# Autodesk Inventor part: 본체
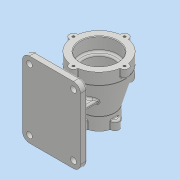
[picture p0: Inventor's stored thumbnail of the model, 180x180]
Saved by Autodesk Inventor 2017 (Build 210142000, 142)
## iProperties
Part Number: 본체
Material: 일반
Document SubType Name: Modeling
Designer: 222
Density: 1 g/cm^3
Appearance: 기본값
Mass: 385.863 g
Surface Area: 850.637 cm^2
Volume: 385.863 cm^3
Author: 222
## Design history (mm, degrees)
sketch "스케치2"
  geometry: L1 (0, 0)-(44, 0); L2 (44, 0)-(44, -20); L3 (44, -20)-(27.5, -78); L4 (27.5, -78)-(27.5, -100); L5 (27.5, -100)-(0, -100); L6 (0, -100)-(0, 0)
  constraints: 12 end point, 3 perpendicular, 1 horizontal, 1 parallel
  dimensions: "d0" = 88 diameter of L2 L6; "d1" = 55 diameter of L4 L6; "d2" = 100 distance of L5.end L1.start; "d4" = 20 distance of L1.end L2.end; "d5" = 22 distance of L3.end L4.end
revolve "회전1" sketch "스케치2" stored, may be unused: angle "d6" = 90 deg
node "작업 평면1"
sketch "스케치3"
  geometry: L1 (50, 15)-(-50, 15); L2 (-50, 15)-(-50, -115); L3 (-50, -115)-(50, -115); L4 (50, -115)-(50, 15); L5 (-44, 0)-(44, 0) reference; 2 further points
  constraints: 8 end point, 2 parallel, 1 horizontal, 1 midpoint, 1 perpendicular, 1 vertical alignment
  dimensions: "d8" = 130 distance of L3.end L1.start; "d9" = 100 distance of L2.end L3.end; "d10" = 15 distance between parallel lines of L1 L5
extrude "돌출1" join sketch "스케치3" distance "d11" = 12; taper "d12" = 0 deg
sketch "스케치6"
  geometry: L1 (-50, -15)-(50, -15) reference; L2 (-50, 115)-(-50, -15) reference; L3 (50, 115)-(-50, 115) reference; L4 (50, -15)-(50, 115) reference; L5 (-25, 46)-(25, 46); L6 (25, 46)-(25, 54); L7 (25, 54)-(-25, 54); L8 (-25, 54)-(-25, 46); L9 (-4, 26)-(4, 26); L10 (4, 26)-(4, 74); L11 (4, 74)-(-4, 74); L12 (-4, 74)-(-4, 26); 6 further points
  constraints: 16 end point, 5 midpoint, 4 parallel, 2 horizontal, 2 horizontal alignment, 2 perpendicular, 2 vertical alignment
  dimensions: "d15" = 8 distance of L7.end L5.start; "d16" = 8 distance of L10.end L11.end; "d17" = 48 distance of L9.end L10.end; "d18" = 50 distance of L6.end L7.end
extrude "돌출2" join sketch "스케치6" stored distance "d19" = 12; taper "d20" = 0 deg
sketch "스케치7"
  geometry: L1 (-7, 43.44)-(-7, 44); L2 (7, 44)-(7, 43.44); A1 r 44 centre (0, 0) between (-7, 43.44) and (7, 43.44) reference; A2 r 7 centre (0, 44) between (7, 44) and (-7, 44); 1 further point
  constraints: 5 point on circle, 4 end point, 2 tangent, 1 centre point, 1 parallel, 1 vertical, 1 vertical alignment
  dimensions: "d21" = 7 radius of A2
extrude "돌출3" join sketch "스케치7" distance "d22" = 15; taper "d23" = 0 deg
sketch "스케치8"
  geometry: L1 (-7, 26.594)-(-7, 27.5); L2 (7, 27.5)-(7, 26.594); A1 r 27.5 centre (0, 0) between (-7, 26.594) and (7, 26.594) reference; A2 r 7 centre (0, 27.5) between (7, 27.5) and (-7, 27.5); 1 further point
  constraints: 5 point on circle, 4 end point, 2 tangent, 2 vertical, 1 centre point, 1 vertical alignment
  dimensions: "d27" = 7 radius of A2
extrude "돌출4" join sketch "스케치8" distance "d28" = 15; taper "d29" = 0 deg
node "작업 평면2"
sketch "스케치9"
  geometry: L1 (7, 0)-(-7, 0) reference; C1 r 17 at (0, -50); 2 further points
  constraints: 1 centre point, 1 midpoint, 1 vertical alignment
  dimensions: "d34" = 34 diameter of C1; "d35" = 50 distance from line of C1.centre L1
extrude "돌출5" join sketch "스케치9" stored distance "d36" = 15; taper "d37" = 0 deg
hole "구멍1" diameter "d40" = 52; stored, may be unused: countersink angle "d44" = 90 deg, drill point angle "d46" = 0 deg; dims "d38" = 10, "d39" = 10, "d41" = 6, "d42" = 64, "d43" = 23, "d45" = 70
hole "구멍2" diameter "d49" = 40; stored, may be unused: countersink angle "d53" = 90 deg, drill point angle "d55" = 0 deg; dims "d47" = 10, "d48" = 10, "d50" = 6, "d51" = 20, "d52" = 23, "d54" = 30
hole "구멍3" diameter "d58" = 22; stored, may be unused: countersink angle "d62" = 90 deg, drill point angle "d64" = 0 deg; dims "d56" = 10, "d57" = 10, "d59" = 6, "d60" = 28, "d61" = 1, "d63" = 30
sketch "스케치10"
  geometry: A1 r 44 centre (0, -44) between (7, -0.56) and (-7, -0.56) reference; 3 further points
  constraints: 1 coincident, 1 point on circle, 1 vertical alignment
hole "구멍4" sketch "스케치10" at (0, 0) diameter "d65" = 4.134; stored, may be unused: countersink angle "d69" = 90 deg, drill point angle "d71" = 118 deg; dims "d66" = 9, "d67" = 28, "d68" = 1, "d70" = 11
sketch "스케치11"
  geometry: A1 r 27.5 centre (0, -27.5) between (7, -0.906) and (-7, -0.906) reference; 3 further points
  constraints: 1 coincident, 1 point on circle, 1 vertical alignment
hole "구멍5" sketch "스케치11" at (0, 0) diameter "d75" = 4.134; stored, may be unused: countersink angle "d79" = 90 deg, drill point angle "d81" = 118 deg; dims "d76" = 9, "d77" = 28, "d78" = 1, "d80" = 11
sketch "스케치12"
  geometry: L1 (50, -15)-(50, 115) reference; L2 (50, 115)-(-50, 115) reference; 2 further points
  constraints: 1 other
  dimensions: "d85" = 10 distance from line of point (40, 50) L1; "d86" = 65 distance from line of point (40, 50) L2
feature "엠보싱1" sketch "스케치12" dims "d0" = 88, "d1" = 55, "d2" = 100, "d4" = 20, "d5" = 22, "d87" = 0.5, "d88" = 0
fillet "모깎기1" dims "d89" = 12
sketch "스케치13"
  geometry: L1 (-50, 103)-(-50, -3) reference; L2 (38, 115)-(-38, 115) reference; L3 (50, -3)-(50, 103) reference; L4 (-38, -15)-(38, -15) reference; A1 r 12 centre (-38, -3) between (-50, -3) and (-38, -15) reference; A2 r 12 centre (-38, 103) between (-38, 115) and (-50, 103) reference; A3 r 12 centre (38, 103) between (50, 103) and (38, 115) reference; A4 r 12 centre (38, -3) between (38, -15) and (50, -3) reference; 5 further points
  constraints: 4 coincident
hole "구멍6" sketch "스케치13" at (-38, -3), (-38, 103), (38, -3), (38, 103) diameter "d90" = 10; stored, may be unused: countersink angle "d94" = 90 deg, drill point angle "d96" = 0 deg; dims "d91" = 9, "d92" = 28, "d93" = 1, "d95" = 11
fillet "모깎기2" dims "d97" = 3
fillet "모깎기3" dims "d98" = 3
fillet "모깎기4" dims "d99" = 1
fillet "모깎기5" dims "d100" = 3
chamfer "모따기1" distance "d101" = 1; stored, may be unused: second distance "d102" = 2, angle "d103" = 45 deg
node "솔리드1"
pattern_circular "원형 패턴1" dims angle "d25" = 360 deg
pattern_circular "원형 패턴2" dims angle "d31" = 360 deg
pattern_circular "원형 패턴3" dims angle "d73" = 360 deg
pattern_circular "원형 패턴4" dims angle "d83" = 360 deg
node "투영된 루프1"
node "투영된 루프2"
node "투영된 루프3"
other parameters: "d7" = -82, "d33" = 45
